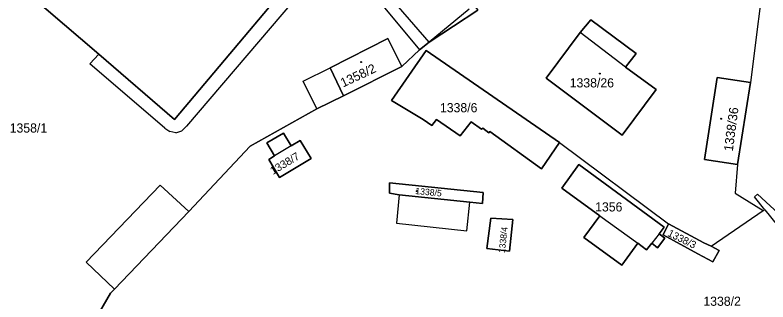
# Model space of a CAD drawing. Extents: x -598934 to -598196, y -1162208 to -1161502.
# Drawn here: x -598445.3 to -598305.5, y -1161757.9 to -1161704.6 of the extents above; entities that cross this region are included whole.
import ezdxf

# ---------------------------------------------------------------- set-up
doc = ezdxf.new("R2010")
doc.units = 0
for name, color, linetype in [('KN_CAR_KR', 7, 'Continuous'), ('KN_KULTURY', 7, 'Continuous'), ('KN_PARC_CIS_POZ', 7, 'Continuous'), ('KN_PARC_CIS_STAV', 7, 'Continuous'), ('KN_PARC_PLOCHA', 7, 'Continuous'), ('parcely_l', 7, 'Continuous')]:
    doc.layers.add(name, color=color, linetype=linetype)

msp = doc.modelspace()

# ---------------------------------------------------------------- linework, layer by layer
at = {"layer": 'KN_CAR_KR'}
for points in [[(-598384.54, -1161691.34), (-598413.43, -1161725.26)], [(-598305.85, -1161693.93), (-598308.81, -1161717.15)], [(-598368.4, -1161709.66), (-598376.98, -1161699.71)], [(-598378.53, -1161701.03), (-598370.21, -1161711.06)], [(-598361.01, -1161703.52), (-598368.4, -1161709.66)], [(-598331.96, -1161714.29), (-598340.38, -1161707.86)], [(-598431.39, -1161713.67), (-598429.74, -1161711.85)], [(-598417.49, -1161725.61), (-598431.39, -1161713.67)], [(-598391.8, -1161716.88), (-598386.82, -1161714.43)], [(-598389.25, -1161722.01), (-598391.8, -1161716.88)], [(-598413.43, -1161725.26), (-598414.3, -1161726.1)], [(-598417.49, -1161725.61), (-598416.57, -1161726.28)], [(-598415.41, -1161726.47), (-598416.57, -1161726.28)], [(-598415.41, -1161726.47), (-598414.3, -1161726.1)], [(-598394.04, -1161728.93), (-598397.1, -1161730.77)], [(-598344.21, -1161728.32), (-598323.98, -1161743.42)], [(-598311.17, -1161732.4), (-598311.63, -1161737.69)], [(-598418.33, -1161736.22), (-598432.08, -1161750.56)], [(-598413, -1161741.14), (-598418.33, -1161736.22)], [(-598311.63, -1161737.69), (-598306.43, -1161740.96)], [(-598308.07, -1161738.36), (-598307.47, -1161737.89)], [(-598307.47, -1161737.89), (-598302.81, -1161742.23)], [(-598373.97, -1161738.01), (-598374.51, -1161743.27)], [(-598306.13, -1161740.78), (-598308.07, -1161738.36)], [(-598361.44, -1161744.69), (-598360.89, -1161739.37)], [(-598336.74, -1161741.91), (-598329.72, -1161747)], [(-598316.11, -1161747.57), (-598306.43, -1161740.96)], [(-598306.43, -1161740.96), (-598306.13, -1161740.78)], [(-598306.13, -1161740.78), (-598303.77, -1161743.74)], [(-598374.51, -1161743.27), (-598361.44, -1161744.69)], [(-598325.75, -1161745.26), (-598327.07, -1161746.99)], [(-598432.08, -1161750.56), (-598426.83, -1161755.55)]]:
    msp.add_lwpolyline(points, dxfattribs=at)
at = {"layer": 'KN_KULTURY'}
for centre, radius in [((-598381.04, -1161713.36), 0.09), ((-598381.04, -1161713.36), 0.0398), ((-598336.75, -1161715.49), 0.09), ((-598336.75, -1161715.49), 0.0398), ((-598314.21, -1161723.89), 0.09), ((-598314.21, -1161723.89), 0.0398), ((-598370.73, -1161737.31), 0.09), ((-598370.73, -1161737.31), 0.0398)]:
    msp.add_circle(centre, radius, dxfattribs=at)
at = {"layer": 'KN_PARC_PLOCHA'}
for points in [[(-598492.06, -1161676.4), (-598438.63, -1161618.4), (-598435.81, -1161615.34), (-598428.76, -1161622.69), (-598430.79, -1161624.72), (-598409.66, -1161643.2), (-598396.69, -1161658.7), (-598384.62, -1161673.23), (-598380.84, -1161677.59), (-598359.36, -1161703.7), (-598368.4, -1161709.66), (-598370.21, -1161711.06), (-598373.51, -1161714.16), (-598376.07, -1161708.98), (-598386.82, -1161714.43), (-598384.3, -1161719.62), (-598389.25, -1161722.01), (-598401.62, -1161728.95), (-598413, -1161741.14), (-598426.83, -1161755.55), (-598427.55, -1161756.32), (-598440.02, -1161777.77)], [(-598440.02, -1161777.77), (-598427.55, -1161756.32), (-598426.83, -1161755.55), (-598413, -1161741.14), (-598401.62, -1161728.95), (-598389.25, -1161722.01), (-598384.3, -1161719.62), (-598373.51, -1161714.16), (-598370.21, -1161711.06), (-598368.4, -1161709.66), (-598359.36, -1161703.7)]]:
    msp.add_lwpolyline(points, dxfattribs=at)
for points in [[(-598386.18, -1161688.92), (-598402.15, -1161675.09), (-598422.44, -1161657.68), (-598422.42, -1161657.49), (-598430.84, -1161650.19), (-598461.34, -1161685.01), (-598452.94, -1161692.42), (-598452.73, -1161692.19), (-598429.74, -1161711.85), (-598415.67, -1161724.01)], [(-598386.18, -1161688.92), (-598415.67, -1161724.01), (-598429.74, -1161711.85), (-598452.73, -1161692.19), (-598452.94, -1161692.42), (-598461.34, -1161685.01), (-598430.84, -1161650.19), (-598422.42, -1161657.49), (-598422.44, -1161657.68), (-598402.15, -1161675.09)], [(-598326.27, -1161718.47), (-598332.62, -1161726.92), (-598346.72, -1161716.32), (-598340.38, -1161707.86), (-598338.43, -1161705.52), (-598330, -1161711.74), (-598331.96, -1161714.29)], [(-598326.27, -1161718.47), (-598331.96, -1161714.29), (-598330, -1161711.74), (-598338.43, -1161705.52), (-598340.38, -1161707.86), (-598346.72, -1161716.32), (-598332.62, -1161726.92)], [(-598373.51, -1161714.16), (-598384.3, -1161719.62), (-598386.82, -1161714.43), (-598376.07, -1161708.98)], [(-598368.95, -1161711.17), (-598344.21, -1161728.32), (-598347.59, -1161733.19), (-598357.14, -1161726.27), (-598357.35, -1161726.49), (-598358.49, -1161725.63), (-598358.72, -1161725.84), (-598360.6, -1161724.45), (-598362.66, -1161727.05), (-598367.07, -1161723.99), (-598367.93, -1161725.11), (-598369.54, -1161724.04), (-598375.42, -1161720.5)], [(-598368.95, -1161711.17), (-598375.42, -1161720.5), (-598369.54, -1161724.04), (-598367.93, -1161725.11), (-598367.07, -1161723.99), (-598362.66, -1161727.05), (-598360.6, -1161724.45), (-598358.72, -1161725.84), (-598358.49, -1161725.63), (-598357.35, -1161726.49), (-598357.14, -1161726.27), (-598347.59, -1161733.19), (-598344.21, -1161728.32)], [(-598308.81, -1161717.15), (-598311.17, -1161732.4), (-598317.35, -1161731.43), (-598314.98, -1161716.23)], [(-598308.81, -1161717.15), (-598314.98, -1161716.23), (-598317.35, -1161731.43), (-598311.17, -1161732.4)], [(-598395.48, -1161726.57), (-598394.04, -1161728.93), (-598392.35, -1161727.91), (-598390.32, -1161731.29), (-598396.17, -1161734.81), (-598398.2, -1161731.43), (-598397.1, -1161730.77), (-598398.57, -1161728.37)], [(-598395.48, -1161726.57), (-598398.57, -1161728.37), (-598397.1, -1161730.77), (-598398.2, -1161731.43), (-598396.17, -1161734.81), (-598390.32, -1161731.29), (-598392.35, -1161727.91), (-598394.04, -1161728.93)], [(-598324.69, -1161746.09), (-598326.02, -1161747.84), (-598327.07, -1161746.99), (-598328.06, -1161748.21), (-598329.72, -1161747), (-598332.67, -1161751.06), (-598339.69, -1161745.96), (-598336.74, -1161741.91), (-598343.8, -1161736.78), (-598340.66, -1161732.4), (-598324.82, -1161744), (-598325.75, -1161745.26)], [(-598324.69, -1161746.09), (-598325.75, -1161745.26), (-598324.82, -1161744), (-598340.66, -1161732.4), (-598343.8, -1161736.78), (-598336.74, -1161741.91), (-598339.69, -1161745.96), (-598332.67, -1161751.06), (-598329.72, -1161747), (-598328.06, -1161748.21), (-598327.07, -1161746.99), (-598326.02, -1161747.84)], [(-598358.38, -1161737.61), (-598358.5, -1161739.6), (-598360.89, -1161739.37), (-598373.97, -1161738.01), (-598375.81, -1161737.68), (-598375.76, -1161735.8)], [(-598358.38, -1161737.61), (-598375.76, -1161735.8), (-598375.81, -1161737.68), (-598373.97, -1161738.01), (-598360.89, -1161739.37), (-598358.5, -1161739.6)], [(-598352.9, -1161742.6), (-598353.52, -1161748.46), (-598357.7, -1161748.01), (-598356.97, -1161742.33)], [(-598352.9, -1161742.6), (-598356.97, -1161742.33), (-598357.7, -1161748.01), (-598353.52, -1161748.46)], [(-598314.63, -1161748.35), (-598315.75, -1161750.47), (-598318.59, -1161748.96), (-598324.97, -1161745.46), (-598323.98, -1161743.42), (-598317.45, -1161746.91), (-598316.11, -1161747.57)], [(-598314.63, -1161748.35), (-598316.11, -1161747.57), (-598317.45, -1161746.91), (-598323.98, -1161743.42), (-598324.97, -1161745.46), (-598318.59, -1161748.96), (-598315.75, -1161750.47)]]:
    msp.add_lwpolyline(points, close=True, dxfattribs=at)
at = {"layer": 'parcely_l'}
for points in [[(-598386.18, -1161688.92), (-598415.67, -1161724.01), (-598429.74, -1161711.85), (-598452.73, -1161692.19), (-598452.94, -1161692.42), (-598461.34, -1161685.01), (-598430.84, -1161650.19), (-598422.42, -1161657.49), (-598422.44, -1161657.68), (-598402.15, -1161675.09), (-598386.18, -1161688.92)], [(-598373.51, -1161714.16), (-598370.21, -1161711.06), (-598368.4, -1161709.66), (-598359.36, -1161703.7)], [(-598326.27, -1161718.47), (-598331.96, -1161714.29), (-598330, -1161711.74), (-598338.43, -1161705.52), (-598340.38, -1161707.86), (-598346.72, -1161716.32), (-598332.62, -1161726.92), (-598326.27, -1161718.47)], [(-598384.3, -1161719.62), (-598386.82, -1161714.43), (-598376.07, -1161708.98), (-598373.51, -1161714.16)], [(-598368.95, -1161711.17), (-598375.42, -1161720.5), (-598369.54, -1161724.04), (-598367.93, -1161725.11), (-598367.07, -1161723.99), (-598362.66, -1161727.05), (-598360.6, -1161724.45), (-598358.72, -1161725.84), (-598358.49, -1161725.63), (-598357.35, -1161726.49), (-598357.14, -1161726.27), (-598347.59, -1161733.19), (-598344.21, -1161728.32), (-598368.95, -1161711.17)], [(-598384.3, -1161719.62), (-598373.51, -1161714.16)], [(-598308.81, -1161717.15), (-598314.98, -1161716.23), (-598317.35, -1161731.43), (-598311.17, -1161732.4), (-598308.81, -1161717.15)], [(-598440.02, -1161777.77), (-598427.55, -1161756.32), (-598426.83, -1161755.55), (-598413, -1161741.14), (-598401.62, -1161728.95), (-598389.25, -1161722.01), (-598384.3, -1161719.62)], [(-598395.48, -1161726.57), (-598398.57, -1161728.37), (-598397.1, -1161730.77), (-598398.2, -1161731.43), (-598396.17, -1161734.81), (-598390.32, -1161731.29), (-598392.35, -1161727.91), (-598394.04, -1161728.93), (-598395.48, -1161726.57)], [(-598324.69, -1161746.09), (-598325.75, -1161745.26), (-598324.82, -1161744), (-598340.66, -1161732.4), (-598343.8, -1161736.78), (-598336.74, -1161741.91), (-598339.69, -1161745.96), (-598332.67, -1161751.06), (-598329.72, -1161747), (-598328.06, -1161748.21), (-598327.07, -1161746.99), (-598326.02, -1161747.84), (-598324.69, -1161746.09)], [(-598358.38, -1161737.61), (-598375.76, -1161735.8), (-598375.81, -1161737.68), (-598373.97, -1161738.01), (-598360.89, -1161739.37), (-598358.5, -1161739.6), (-598358.38, -1161737.61)], [(-598352.9, -1161742.6), (-598356.97, -1161742.33), (-598357.7, -1161748.01), (-598353.52, -1161748.46), (-598352.9, -1161742.6)], [(-598314.63, -1161748.35), (-598316.11, -1161747.57), (-598317.45, -1161746.91), (-598323.98, -1161743.42), (-598324.97, -1161745.46), (-598318.59, -1161748.96), (-598315.75, -1161750.47), (-598314.63, -1161748.35)]]:
    msp.add_lwpolyline(points, dxfattribs=at)

# ---------------------------------------------------------------- texts
at = {"layer": 'KN_PARC_CIS_POZ'}
for s, p in [('1338/6', (-598366.42, -1161722.68)), ('1356', (-598337.62, -1161741.11))]:
    msp.add_text(s, height=1.7, dxfattribs=at).set_placement(p)
for s, height, rotation, p in [('1338/7', 1.45, 31.1327, (-598397.4, -1161734.34)), ('1338/4', 1.19, 83.5765, (-598354.38, -1161748.89)), ('1338/3', 1.36, 333.759, (-598324.28, -1161745.6))]:
    msp.add_text(s, height=height, rotation=rotation, dxfattribs=at).set_placement(p)
at = {"layer": 'KN_PARC_CIS_STAV'}
for s, height, rotation, p in [('1358/2', 1.7, 25.2002, (-598384.4, -1161718.08)), ('1338/36', 1.7, 82.5322, (-598312.07, -1161730.01)), ('1338/5', 1.2, 354.5994, (-598371.03, -1161737.87))]:
    msp.add_text(s, height=height, rotation=rotation, dxfattribs=at).set_placement(p)
for s, p in [('1338/26', (-598342.34, -1161718.06)), ('1358/1', (-598446.27, -1161726.45)), ('1338/2', (-598317.53, -1161758.64))]:
    msp.add_text(s, height=1.7, dxfattribs=at).set_placement(p)

doc.saveas('drawing.dxf')
